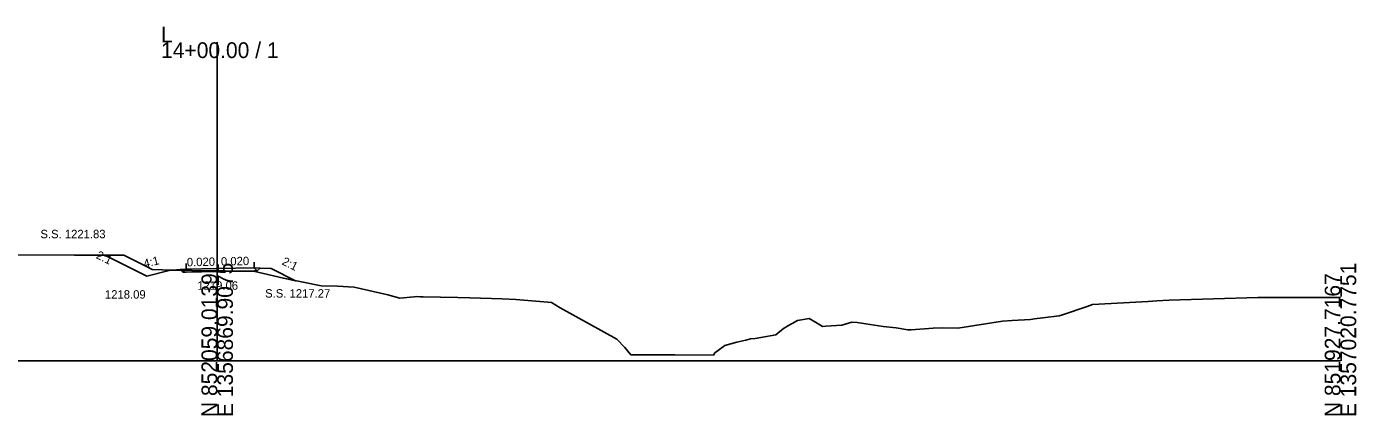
# Model space of a CAD drawing. Extents: x -26 to 4603, y -10 to 4066.
# Drawn here: x 166.1 to 402.8, y 3490.3 to 3559.5 of the extents above; entities that cross this region are included whole.
import ezdxf

# ---------------------------------------------------------------- set-up
doc = ezdxf.new("R2010")
doc.units = 0
for name, color, linetype in [('Exist Cross Section Cell', 7, 'Continuous'), ('Exist XS Center Line Elevation Label', 7, 'Continuous'), ('Exist XS Ground Line', 7, 'Continuous'), ('Prop XS Ditch Slope Text', 7, 'Continuous'), ('Prop XS Ditch Standard Text', 7, 'Continuous'), ('Prop XS Dump Level', 7, 'Continuous'), ('Prop XS Earthwork Shape', 7, 'Continuous'), ('Prop XS EOT Tick Mark', 7, 'Continuous'), ('Prop XS Finish Grade', 7, 'Continuous'), ('Prop XS Finish Grade Earthwork', 7, 'Continuous'), ('Prop XS Finish Grade Pavement', 7, 'Continuous'), ('Prop XS Pvmt Edge Slope', 7, 'Continuous'), ('Prop XS SE Text', 7, 'Continuous'), ('Prop XS Side Slope Text', 7, 'Continuous'), ('Prop XS SS Elevation Text', 7, 'Continuous'), ('Prop XS Subgrade Earthwork', 7, 'Continuous')]:
    doc.layers.add(name, color=color, linetype=linetype)

msp = doc.modelspace()

# ---------------------------------------------------------------- linework, layer by layer
at = {"layer": 'Exist Cross Section Cell'}
for p, q in [((200, 3500), (200, 3556.71)), ((0, 3500), (200, 3500)), ((200, 3500), (400, 3500))]:
    msp.add_line(p, q, dxfattribs=at)
at = {"layer": 'Exist XS Ground Line'}
for p, q in [((163.5, 3518.87), (174.59, 3518.84)), ((174.59, 3518.84), (183.37, 3518.82)), ((183.37, 3518.82), (187.4, 3516.78)), ((187.4, 3516.78), (188.4, 3516.26)), ((188.4, 3516.26), (190.27, 3516.21)), ((190.27, 3516.21), (195.47, 3516.1)), ((195.47, 3516.1), (200, 3516.06)), ((200, 3516.06), (201.41, 3516.04)), ((201.41, 3516.04), (206.43, 3515.97)), ((206.43, 3515.97), (211.78, 3514.71)), ((211.78, 3514.71), (218.51, 3513.37)), ((218.51, 3513.37), (221.44, 3513.28)), ((221.44, 3513.28), (224.41, 3513.15)), ((224.41, 3513.15), (230.37, 3511.74)), ((230.37, 3511.74), (232.5, 3511.2)), ((232.5, 3511.2), (235.05, 3511.41)), ((235.05, 3511.41), (235.57, 3511.44)), ((235.57, 3511.44), (236.13, 3511.43)), ((236.13, 3511.43), (236.68, 3511.41)), ((236.68, 3511.41), (242.87, 3511.27)), ((242.87, 3511.27), (244.95, 3511.26)), ((244.95, 3511.26), (250.74, 3511.05)), ((250.74, 3511.05), (253.18, 3510.93)), ((253.18, 3510.93), (258.86, 3510.45)), ((258.86, 3510.45), (259.52, 3510.41)), ((259.52, 3510.41), (261.07, 3509.47)), ((261.07, 3509.47), (271.17, 3503.9)), ((350.53, 3508.23), (354.92, 3509.69)), ((354.92, 3509.69), (355.87, 3510.03)), ((355.87, 3510.03), (365.74, 3510.57)), ((365.74, 3510.57), (367.3, 3510.7)), ((367.3, 3510.7), (369.48, 3510.82)), ((369.48, 3510.82), (385.31, 3511.27)), ((385.31, 3511.27), (389.87, 3511.27)), ((389.87, 3511.27), (400, 3511.27)), ((302.38, 3506.67), (303.32, 3507.2)), ((303.32, 3507.2), (305.38, 3507.58)), ((305.38, 3507.58), (306.82, 3506.73)), ((311.19, 3506.36), (312.98, 3506.9)), ((312.98, 3506.9), (313.97, 3506.85)), ((313.97, 3506.85), (318.58, 3506.12)), ((331.89, 3505.84), (339.84, 3507.07)), ((339.84, 3507.07), (341.56, 3507.21)), ((341.56, 3507.21), (344.83, 3507.39)), ((344.83, 3507.39), (345.51, 3507.47)), ((345.51, 3507.47), (347.01, 3507.66)), ((347.01, 3507.66), (349.91, 3508.02)), ((349.91, 3508.02), (350.53, 3508.23)), ((296.82, 3504.2), (299.46, 3504.65)), ((299.46, 3504.65), (300.83, 3505.8)), ((300.83, 3505.8), (301.26, 3506.03)), ((301.26, 3506.03), (301.6, 3506.24)), ((301.6, 3506.24), (302.38, 3506.67)), ((306.82, 3506.73), (307.78, 3506.15)), ((307.78, 3506.15), (308.39, 3506.19)), ((308.39, 3506.19), (311.19, 3506.36)), ((318.58, 3506.12), (320.88, 3505.9)), ((320.88, 3505.9), (322.99, 3505.55)), ((322.99, 3505.55), (323.59, 3505.52)), ((323.59, 3505.52), (327.45, 3505.86)), ((327.45, 3505.86), (329.12, 3505.88)), ((329.12, 3505.88), (331.89, 3505.84)), ((271.17, 3503.9), (272.59, 3502.38)), ((272.59, 3502.38), (273.62, 3501.08)), ((288.59, 3501.44), (290.39, 3502.73)), ((290.39, 3502.73), (291.47, 3503.03)), ((291.47, 3503.03), (292.52, 3503.37)), ((292.52, 3503.37), (294.13, 3503.68)), ((294.13, 3503.68), (294.98, 3503.95)), ((294.98, 3503.95), (295.76, 3504.02)), ((295.76, 3504.02), (296.82, 3504.2)), ((273.62, 3501.08), (274.37, 3501.08)), ((274.37, 3501.08), (281.49, 3501.08)), ((281.49, 3501.08), (288.34, 3501.05)), ((288.34, 3501.05), (288.59, 3501.44))]:
    msp.add_line(p, q, dxfattribs=at)
at = {"layer": 'Prop XS Dump Level'}
for p, q in [((194.45, 3516.33), (200, 3516.44)), ((200, 3516.44), (206.6, 3516.57))]:
    msp.add_line(p, q, dxfattribs=at)
at = {"layer": 'Prop XS Earthwork Shape'}
for points in [[(192.4, 3516.17), (191.45, 3516.09), (187.45, 3515.09), (179.98, 3518.83), (183.37, 3518.82), (187.4, 3516.78), (188.4, 3516.26), (190.27, 3516.21)], [(192.4, 3516.17), (191.45, 3516.09), (187.45, 3515.09), (179.98, 3518.83), (183.37, 3518.82), (187.4, 3516.78), (188.4, 3516.26), (190.27, 3516.21)], [(193.53, 3516.14), (193.42, 3516.25), (192.4, 3516.17)], [(193.53, 3516.14), (193.42, 3516.25), (192.4, 3516.17)], [(204.79, 3516), (206.43, 3515.97), (211.78, 3514.71), (213.96, 3514.27), (209.6, 3516.45), (207.62, 3516.53), (207.13, 3516.04), (206.6, 3516.03)], [(204.79, 3516), (206.43, 3515.97), (211.78, 3514.71), (213.96, 3514.27), (209.6, 3516.45), (207.62, 3516.53), (207.13, 3516.04), (206.6, 3516.03)], [(204.79, 3516), (200, 3515.9), (194.45, 3515.79), (193.89, 3515.78), (193.53, 3516.14), (195.47, 3516.1), (200, 3516.06), (201.41, 3516.04)], [(204.79, 3516), (200, 3515.9), (194.45, 3515.79), (193.89, 3515.78), (193.53, 3516.14), (195.47, 3516.1), (200, 3516.06), (201.41, 3516.04)]]:
    msp.add_lwpolyline(points, close=True, dxfattribs=at)
at = {"layer": 'Prop XS EOT Tick Mark'}
for p, q in [((194.45, 3516.33), (194.45, 3517.33)), ((206.6, 3516.57), (206.6, 3517.57))]:
    msp.add_line(p, q, dxfattribs=at)
at = {"layer": 'Prop XS Finish Grade'}
for p, q in [((194.45, 3516.33), (193.42, 3516.25)), ((206.6, 3516.57), (207.62, 3516.53))]:
    msp.add_line(p, q, dxfattribs=at)
at = {"layer": 'Prop XS Finish Grade Earthwork'}
for p, q in [((187.45, 3515.09), (179.98, 3518.83)), ((193.42, 3516.25), (191.45, 3516.09)), ((207.62, 3516.53), (209.6, 3516.45)), ((209.6, 3516.45), (213.96, 3514.27)), ((191.45, 3516.09), (187.45, 3515.09))]:
    msp.add_line(p, q, dxfattribs=at)
at = {"layer": 'Prop XS Finish Grade Pavement'}
for p, q in [((194.45, 3516.33), (200, 3516.44)), ((200, 3516.44), (206.6, 3516.57))]:
    msp.add_line(p, q, dxfattribs=at)
at = {"layer": 'Prop XS Pvmt Edge Slope'}
for p, q in [((194.45, 3516.33), (193.89, 3515.78)), ((206.6, 3516.57), (207.13, 3516.04))]:
    msp.add_line(p, q, dxfattribs=at)
at = {"layer": 'Prop XS Subgrade Earthwork'}
for p, q in [((193.89, 3515.78), (193.42, 3516.25)), ((207.13, 3516.04), (207.62, 3516.53)), ((194.45, 3515.79), (193.89, 3515.78)), ((200, 3515.9), (194.45, 3515.79)), ((206.6, 3516.03), (200, 3515.9)), ((206.6, 3516.03), (207.13, 3516.04))]:
    msp.add_line(p, q, dxfattribs=at)

# ---------------------------------------------------------------- texts
at = {"layer": 'Exist Cross Section Cell'}
for s, p in [('L', (190, 3556.71)), ('14+00.00 / 1', (190, 3553.91))]:
    msp.add_text(s, height=2.8, dxfattribs=at).set_placement(p)
for s, p in [('E 1356869.9075', (202.8, 3490)), ('E 1357020.7751', (402.8, 3490)), ('N 852059.0139', (200, 3490)), ('N 851927.7167', (400, 3490))]:
    msp.add_text(s, height=2.8, rotation=90, dxfattribs=at).set_placement(p)
at = {"layer": 'Exist XS Center Line Elevation Label'}
msp.add_text('1219.06', height=1.5, dxfattribs=at).set_placement((196.46, 3512.67))
at = {"layer": 'Prop XS Ditch Slope Text'}
msp.add_text('4:1', height=1.5, rotation=14.0362, dxfattribs=at).set_placement((187.08, 3516.55))
at = {"layer": 'Prop XS Ditch Standard Text'}
msp.add_text('1218.09', height=1.5, dxfattribs=at).set_placement((180.01, 3511.09))
at = {"layer": 'Prop XS Dump Level'}
for p in [(209.6, 3516.41), (191.45, 3516.05)]:
    msp.add_text('Case1', height=0.04, dxfattribs=at).set_placement(p)
at = {"layer": 'Prop XS SE Text'}
for p in [(194.6, 3516.83), (200.68, 3516.96)]:
    msp.add_text('0.020', height=1.5, rotation=1.1458, dxfattribs=at).set_placement(p)
at = {"layer": 'Prop XS Side Slope Text'}
for p in [(178.3, 3518.34), (211.39, 3517.24)]:
    msp.add_text('2:1', height=1.5, rotation=333.4349, dxfattribs=at).set_placement(p)
at = {"layer": 'Prop XS SS Elevation Text'}
for s, p in [('S.S. 1221.83', (168.52, 3521.84)), ('S.S. 1217.27', (208.53, 3511.27))]:
    msp.add_text(s, height=1.5, dxfattribs=at).set_placement(p)

doc.saveas('drawing.dxf')
